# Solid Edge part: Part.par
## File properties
Author: CADCIM
Template: normal.par
Last saved by: Ashutosh-CADCIM
Revision: 17
Application: Solid Edge
Accuracy: 0.99
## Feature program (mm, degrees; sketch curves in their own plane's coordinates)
sketch for "unnamed Protrusion 1" plane through (0, 0, 0) normal (0, 0, 1) x-axis (1, 0, 0)
  line (-63.0032, 49) -> (-56, -71)
  line (-56, -71) -> (56, -71)
  line (56, -71) -> (63.0032, 49)
  line (63.0032, 49) -> (0, 54)
  line (0, 54) -> (-63.0032, 49)
  dimension (linear) = 56
  dimension (linear) = 56
extrude "unnamed Protrusion 1" add finite 4 along +normal
fillet "Round_1" radius 15
sketch for "ExtrudedProtrusion_3" plane through (0, -8.5, 0) normal (0, 0, -1) x-axis (-1, 0, 0)
extrude "ExtrudedProtrusion_3" add finite 12 along -normal
pattern "unnamed Pattern 1" of "ExtrudedProtrusion_3"
pattern "unnamed Pattern 2"
sketch for "unnamed Protrusion 2" plane through (-1.0316, 2.3101, 4) normal (0, 0, 1) x-axis (-1, 0, 0)
extrude "unnamed Protrusion 2" add finite 5 along +normal
sketch for "Hole_22" plane through (40.9331, -54.9887, 12) normal (0, 0, 1) x-axis (1, 0, 0)
  hole centre (-0.4331, -0.0113) bore radius 4.5
hole "Hole_22" diameter 9 through  CounterBoreDepth = 5 mm
pattern "unnamed Pattern 3" of "Hole_22"
hole "unnamed Hole 1" through
hole "unnamed Hole 2" through
hole "unnamed Hole 3" through
sketch for "Hole_29" plane through (-1.0316, -6.1899, 9) normal (0, 0, 1) x-axis (1, 0, 0)
hole "Hole_29" diameter 22 through
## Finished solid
Body 1: solid body, 34 faces, 55 edges, 18 vertices.
  Faces by surface: cylinder 18, plane 16
  Edges by curve: circle 36, line 19
Bounding box of the edges (mm): 124.346 x 125.000 x 12.000, from (-62.1729, -71, 0) to (62.1729, 54, 12).
Cylindrical faces by radius (mm): R4.5 x4, R7.5 x4, R10.7006 x4, R11 x1, R15 x4, R20 x1
Planar faces by outward normal: +z 10, -y 1, -z 1, oblique 4
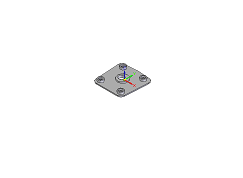
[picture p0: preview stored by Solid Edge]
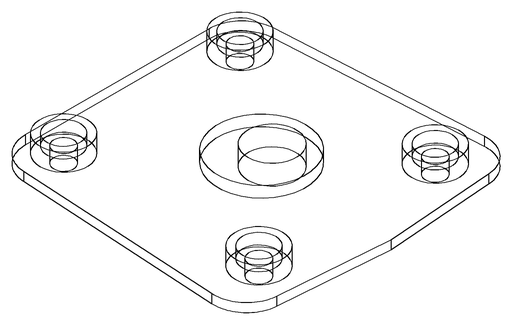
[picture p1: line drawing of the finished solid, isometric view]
